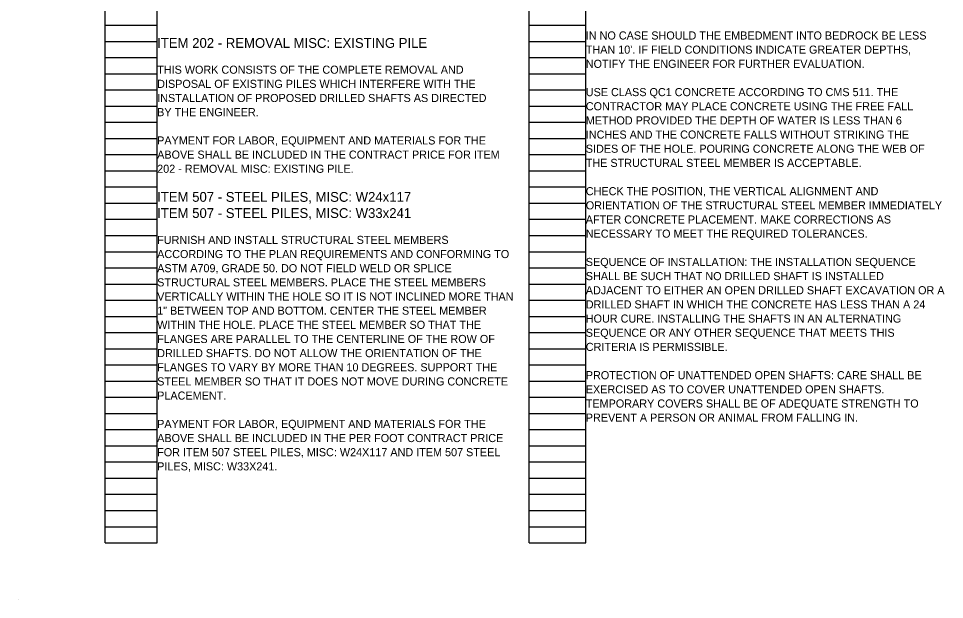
# Model space of a CAD drawing. Extents: x -2.8 to 53.9, y -6 to 15.2.
# Drawn here: x -2.79 to 13.24, y -5.98 to 4.08 of the extents above; entities that cross this region are included whole.
import ezdxf

# ---------------------------------------------------------------- set-up
doc = ezdxf.new("R2010")
doc.units = 0
doc.layers.add('SC_Scratch1', color=7, linetype='Continuous')
doc.layers.add('SH_Text', color=7, linetype='Continuous')

msp = doc.modelspace()

# ---------------------------------------------------------------- linework, layer by layer
at = {"layer": 'SC_Scratch1'}
for p, q in [((-1.287, -4.995), (-1.287, 15.165)), ((-0.387, -4.995), (-0.387, 15.165)), ((6.053, -4.995), (6.053, 15.165)), ((7.033, -4.995), (7.033, 15.165)), ((-1.287, 3.965), (-0.387, 3.965)), ((6.053, 3.965), (7.033, 3.965)), ((-1.287, 3.685), (-0.387, 3.685)), ((6.053, 3.685), (7.033, 3.685)), ((-1.287, 3.405), (-0.387, 3.405)), ((6.053, 3.405), (7.033, 3.405)), ((-1.287, 3.125), (-0.387, 3.125)), ((6.053, 3.125), (7.033, 3.125)), ((-1.287, 2.845), (-0.387, 2.845)), ((6.053, 2.845), (7.033, 2.845)), ((-1.287, 2.565), (-0.387, 2.565)), ((6.053, 2.565), (7.033, 2.565)), ((-1.287, 2.285), (-0.387, 2.285)), ((6.053, 2.285), (7.033, 2.285)), ((-1.287, 2.005), (-0.387, 2.005)), ((6.053, 2.005), (7.033, 2.005)), ((-1.287, 1.725), (-0.387, 1.725)), ((6.053, 1.725), (7.033, 1.725)), ((-1.287, 1.445), (-0.387, 1.445)), ((6.053, 1.445), (7.033, 1.445)), ((-1.287, 1.165), (-0.387, 1.165)), ((6.053, 1.165), (7.033, 1.165)), ((-1.287, 0.885), (-0.387, 0.885)), ((6.053, 0.885), (7.033, 0.885)), ((-1.287, 0.605), (-0.387, 0.605)), ((6.053, 0.605), (7.033, 0.605)), ((-1.287, 0.325), (-0.387, 0.325)), ((6.053, 0.325), (7.033, 0.325)), ((-1.287, 0.045), (-0.387, 0.045)), ((6.053, 0.045), (7.033, 0.045)), ((-1.287, -0.235), (-0.387, -0.235)), ((6.053, -0.235), (7.033, -0.235)), ((-1.287, -0.515), (-0.387, -0.515)), ((6.053, -0.515), (7.033, -0.515)), ((-1.287, -0.795), (-0.387, -0.795)), ((6.053, -0.795), (7.033, -0.795)), ((-1.287, -1.075), (-0.387, -1.075)), ((6.053, -1.075), (7.033, -1.075)), ((-1.287, -1.355), (-0.387, -1.355)), ((6.053, -1.355), (7.033, -1.355)), ((-1.287, -1.635), (-0.387, -1.635)), ((6.053, -1.635), (7.033, -1.635)), ((-1.287, -1.915), (-0.387, -1.915)), ((6.053, -1.915), (7.033, -1.915)), ((-1.287, -2.195), (-0.387, -2.195)), ((6.053, -2.195), (7.033, -2.195)), ((-1.287, -2.475), (-0.387, -2.475)), ((6.053, -2.475), (7.033, -2.475)), ((-1.287, -2.755), (-0.387, -2.755)), ((6.053, -2.755), (7.033, -2.755)), ((-1.287, -3.035), (-0.387, -3.035)), ((6.053, -3.035), (7.033, -3.035)), ((-1.287, -3.315), (-0.387, -3.315)), ((6.053, -3.315), (7.033, -3.315)), ((-1.287, -3.595), (-0.387, -3.595)), ((6.053, -3.595), (7.033, -3.595)), ((-1.287, -3.875), (-0.387, -3.875)), ((6.053, -3.875), (7.033, -3.875)), ((-1.287, -4.155), (-0.387, -4.155)), ((6.053, -4.155), (7.033, -4.155)), ((-1.287, -4.435), (-0.387, -4.435)), ((6.053, -4.435), (7.033, -4.435)), ((-1.287, -4.715), (-0.387, -4.715)), ((6.053, -4.715), (7.033, -4.715)), ((-1.287, -4.995), (-0.387, -4.995)), ((6.053, -4.995), (7.033, -4.995)), ((-2.787, -5.975), (-2.787, -5.975))]:
    msp.add_line(p, q, dxfattribs=at)

# ---------------------------------------------------------------- texts
at = {"layer": 'SH_Text'}
for s, height, p in [('IN NO CASE SHOULD THE EMBEDMENT INTO BEDROCK BE LESS ', 0.14, (7.033, 3.717)), ('ITEM 202 - REMOVAL MISC: EXISTING PILE', 0.17, (-0.387, 3.573)), ("THAN 10'. IF FIELD CONDITIONS INDICATE GREATER DEPTHS, ", 0.14, (7.033, 3.472)), ('NOTIFY THE ENGINEER FOR FURTHER EVALUATION. ', 0.14, (7.033, 3.227)), ('THIS WORK CONSISTS OF THE COMPLETE REMOVAL AND ', 0.14, (-0.387, 3.125)), ('DISPOSAL OF EXISTING PILES WHICH INTERFERE WITH THE ', 0.14, (-0.387, 2.88)), ('INSTALLATION OF PROPOSED DRILLED SHAFTS AS DIRECTED ', 0.14, (-0.387, 2.635)), ('USE CLASS QC1 CONCRETE ACCORDING TO CMS 511. THE ', 0.14, (7.033, 2.737)), ('CONTRACTOR MAY PLACE CONCRETE USING THE FREE FALL ', 0.14, (7.033, 2.492)), ('BY THE ENGINEER. ', 0.14, (-0.387, 2.39)), ('METHOD PROVIDED THE DEPTH OF WATER IS LESS THAN 6 ', 0.14, (7.033, 2.247)), ('INCHES AND THE CONCRETE FALLS WITHOUT STRIKING THE ', 0.14, (7.033, 2.002)), ('PAYMENT FOR LABOR, EQUIPMENT AND MATERIALS FOR THE ', 0.14, (-0.387, 1.9)), ('ABOVE SHALL BE INCLUDED IN THE CONTRACT PRICE FOR ITEM ', 0.14, (-0.387, 1.655)), ('SIDES OF THE HOLE. POURING CONCRETE ALONG THE WEB OF ', 0.14, (7.033, 1.757)), ('THE STRUCTURAL STEEL MEMBER IS ACCEPTABLE. ', 0.14, (7.033, 1.512)), ('202 - REMOVAL MISC: EXISTING PILE.', 0.14, (-0.387, 1.41)), ('CHECK THE POSITION, THE VERTICAL ALIGNMENT AND ', 0.14, (7.033, 1.022)), ('ITEM 507 - STEEL PILES, MISC: W24x117', 0.17, (-0.387, 0.908)), ('ORIENTATION OF THE STRUCTURAL STEEL MEMBER IMMEDIATELY ', 0.14, (7.033, 0.777)), ('ITEM 507 - STEEL PILES, MISC: W33x241', 0.17, (-0.387, 0.628)), ('AFTER CONCRETE PLACEMENT. MAKE CORRECTIONS AS ', 0.14, (7.033, 0.532)), ('FURNISH AND INSTALL STRUCTURAL STEEL MEMBERS ', 0.14, (-0.387, 0.179)), ('NECESSARY TO MEET THE REQUIRED TOLERANCES. ', 0.14, (7.033, 0.287)), ('ACCORDING TO THE PLAN REQUIREMENTS AND CONFORMING TO ', 0.14, (-0.387, -0.066)), ('SEQUENCE OF INSTALLATION: THE INSTALLATION SEQUENCE ', 0.14, (7.033, -0.203)), ('ASTM A709, GRADE 50. DO NOT FIELD WELD OR SPLICE ', 0.14, (-0.387, -0.311)), ('SHALL BE SUCH THAT NO DRILLED SHAFT IS INSTALLED ', 0.14, (7.033, -0.448)), ('STRUCTURAL STEEL MEMBERS. PLACE THE STEEL MEMBERS ', 0.14, (-0.387, -0.556)), ('ADJACENT TO EITHER AN OPEN DRILLED SHAFT EXCAVATION OR A ', 0.14, (7.033, -0.693)), ('VERTICALLY WITHIN THE HOLE SO IT IS NOT INCLINED MORE THAN ', 0.14, (-0.387, -0.801)), ('DRILLED SHAFT IN WHICH THE CONCRETE HAS LESS THAN A 24 ', 0.14, (7.033, -0.938)), ('1" BETWEEN TOP AND BOTTOM. CENTER THE STEEL MEMBER ', 0.14, (-0.387, -1.046)), ('HOUR CURE. INSTALLING THE SHAFTS IN AN ALTERNATING ', 0.14, (7.033, -1.183)), ('WITHIN THE HOLE. PLACE THE STEEL MEMBER SO THAT THE ', 0.14, (-0.387, -1.291)), ('FLANGES ARE PARALLEL TO THE CENTERLINE OF THE ROW OF ', 0.14, (-0.387, -1.536)), ('SEQUENCE OR ANY OTHER SEQUENCE THAT MEETS THIS ', 0.14, (7.033, -1.428)), ('CRITERIA IS PERMISSIBLE. ', 0.14, (7.033, -1.673)), ('DRILLED SHAFTS. DO NOT ALLOW THE ORIENTATION OF THE ', 0.14, (-0.387, -1.781)), ('FLANGES TO VARY BY MORE THAN 10 DEGREES. SUPPORT THE ', 0.14, (-0.387, -2.026)), ('PROTECTION OF UNATTENDED OPEN SHAFTS: CARE SHALL BE ', 0.14, (7.033, -2.163)), ('STEEL MEMBER SO THAT IT DOES NOT MOVE DURING CONCRETE ', 0.14, (-0.387, -2.271)), ('PLACEMENT. ', 0.14, (-0.387, -2.516)), ('EXERCISED AS TO COVER UNATTENDED OPEN SHAFTS. ', 0.14, (7.033, -2.408)), ('TEMPORARY COVERS SHALL BE OF ADEQUATE STRENGTH TO ', 0.14, (7.033, -2.653)), ('PAYMENT FOR LABOR, EQUIPMENT AND MATERIALS FOR THE ', 0.14, (-0.387, -3.006)), ('PREVENT A PERSON OR ANIMAL FROM FALLING IN. ', 0.14, (7.033, -2.898)), ('ABOVE SHALL BE INCLUDED IN THE PER FOOT CONTRACT PRICE ', 0.14, (-0.387, -3.251)), ('FOR ITEM 507 STEEL PILES, MISC: W24X117 AND ITEM 507 STEEL ', 0.14, (-0.387, -3.496)), ('PILES, MISC: W33X241.', 0.14, (-0.387, -3.741))]:
    msp.add_text(s, height=height, dxfattribs=at).set_placement(p)

doc.saveas('drawing.dxf')
